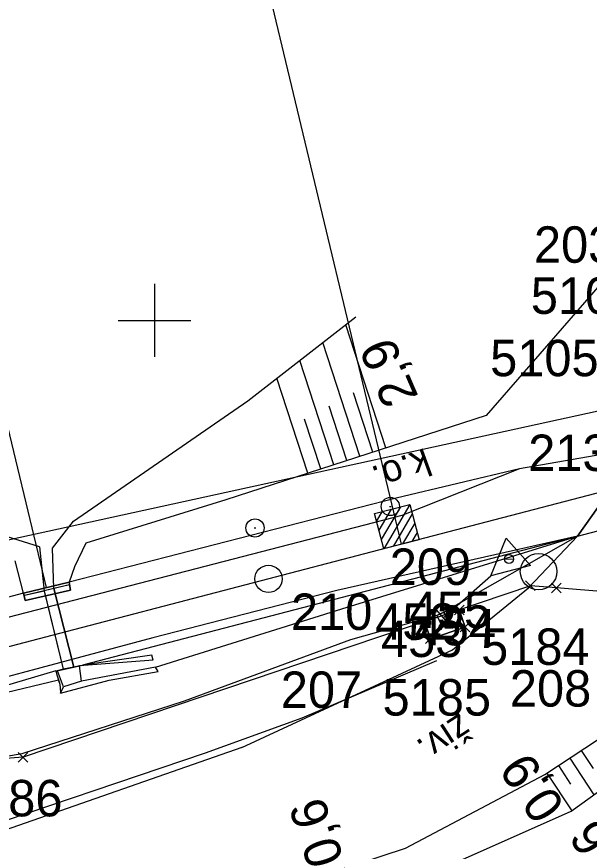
# Model space of a CAD drawing. Extents: x -806456 to -805395, y -1150847 to -1150506.
# Drawn here: x -806207.56 to -806176.16, y -1150729.15 to -1150683.33 of the extents above; entities that cross this region are included whole.
import ezdxf

# ---------------------------------------------------------------- set-up
doc = ezdxf.new("R2010")
doc.units = 0
for name, color, linetype in [('0381KM032-037P - Vrstva 1', 7, 'Continuous'), ('0381KM032-037P - Vrstva 12', 7, 'Continuous'), ('0381KM032-037P - Vrstva 13', 7, 'Continuous'), ('0381KM032-037P - Vrstva 17', 7, 'Continuous'), ('0381KM032-037P - Vrstva 19', 7, 'Continuous'), ('0381KM032-037P - Vrstva 27', 7, 'Continuous'), ('0381KM032-037P - Vrstva 3', 7, 'Continuous'), ('0381KM032-037P - Vrstva 4', 7, 'Continuous'), ('0381KM032-037P - Vrstva 43', 7, 'Continuous'), ('0381KM032-037P - Vrstva 48', 7, 'Continuous'), ('0381KM032-037P - Vrstva 49', 7, 'Continuous'), ('0381KM032-037P - Vrstva 51', 7, 'Continuous'), ('0381KM032-037P - Vrstva 7', 7, 'Continuous'), ('DZ - DZ_krizek', 7, 'Continuous'), ('DZ - DZ_ostat', 7, 'Continuous'), ('DZ - DZ_číslo', 7, 'Continuous'), ('krizky_1000 - Vrstva 1', 7, 'Continuous'), ('szdc - hran DP', 7, 'Continuous'), ('szdc - szdc_cislo', 7, 'Continuous'), ('szdc - szdc_krizek', 7, 'Continuous'), ('VB - VB', 7, 'Continuous'), ('VB - VB_cislo', 7, 'Continuous'), ('VB - VB_krizek', 7, 'Continuous')]:
    doc.layers.add(name, color=color, linetype=linetype)

msp = doc.modelspace()

# ---------------------------------------------------------------- linework, layer by layer
at = {"layer": '0381KM032-037P - Vrstva 1'}
msp.add_lwpolyline([(-805989.76, -1150661.17), (-806027.03, -1150670.9), (-806064.32, -1150680.56), (-806101.67, -1150690.24), (-806138.44, -1150699.75), (-806158.28, -1150704.94), (-806163.64, -1150706.34), (-806175.38, -1150709.4), (-806186.46, -1150712.29), (-806205.201, -1150717.188), (-806213.26, -1150719.29)], dxfattribs=at)
at = {"layer": '0381KM032-037P - Vrstva 12'}
for p, q in [((-806184.517, -1150716.193), (-806184.135, -1150716.013)), ((-806183.852, -1150716.584), (-806183.846, -1150716.582)), ((-806184.236, -1150716.767), (-806184.232, -1150716.767))]:
    msp.add_line(p, q, dxfattribs=at)
msp.add_lwpolyline([(-806184.517, -1150716.196), (-806184.136, -1150716.011), (-806183.846, -1150716.582), (-806184.232, -1150716.767), (-806184.517, -1150716.196), (-806184.517, -1150716.193), (-806184.236, -1150716.767), (-806183.852, -1150716.584), (-806184.135, -1150716.013), (-806184.136, -1150716.011)], dxfattribs=at)
at = {"layer": '0381KM032-037P - Vrstva 13'}
for p, q in [((-806200.148, -1150718.382), (-806203.948, -1150718.928)), ((-806200.065, -1150718.644), (-806200.148, -1150718.382)), ((-806200.065, -1150718.644), (-806204.115, -1150718.971)), ((-806204.115, -1150718.971), (-806203.948, -1150718.928)), ((-806203.996, -1150719.808), (-806204.115, -1150718.971)), ((-806204.985, -1150720.124), (-806205.321, -1150719.23)), ((-806203.996, -1150719.808), (-806204.985, -1150720.124))]:
    msp.add_line(p, q, dxfattribs=at)
for points in [[(-806204.115, -1150718.971), (-806204.42, -1150719.04), (-806205.012, -1150719.152), (-806205.321, -1150719.23)], [(-806205.415, -1150719.241), (-806205.341, -1150719.246), (-806205.321, -1150719.23)], [(-806205.415, -1150719.241), (-806205.331, -1150719.519), (-806205.259, -1150719.74), (-806205.211, -1150719.896), (-806205.18, -1150720.145), (-806205.147, -1150720.463), (-806204.985, -1150720.124)], [(-806205.147, -1150720.463), (-806202.482, -1150719.745), (-806199.79, -1150719.277), (-806199.947, -1150719.038), (-806203.996, -1150719.808)]]:
    msp.add_lwpolyline(points, dxfattribs=at)
at = {"layer": '0381KM032-037P - Vrstva 17'}
msp.add_line((-806191.898, -1150721.811), (-806184.517, -1150718.669), dxfattribs=at)
msp.add_lwpolyline([(-806210.617, -1150728.275), (-806197.196, -1150723.748), (-806191.898, -1150721.811)], dxfattribs=at)
at = {"layer": '0381KM032-037P - Vrstva 19'}
for p, q in [((-806205.929, -1150714.672), (-806217.278, -1150667.349)), ((-806204.679, -1150714.37), (-806207.178, -1150714.973)), ((-806206.05, -1150714.841), (-806205.013, -1150719.154)), ((-806205.518, -1150714.716), (-806205.523, -1150714.718)), ((-806204.418, -1150719.038), (-806205.523, -1150714.718)), ((-806205.518, -1150714.716), (-806204.42, -1150719.04)), ((-806204.606, -1150714.816), (-806204.652, -1150714.519)), ((-806206.05, -1150714.858), (-806207.127, -1150715.107)), ((-806207.086, -1150715.378), (-806207.127, -1150715.107)), ((-806206.05, -1150714.858), (-806205.012, -1150719.152)), ((-806205.013, -1150719.154), (-806204.418, -1150719.038))]:
    msp.add_line(p, q, dxfattribs=at)
for points in [[(-806204.682, -1150714.372), (-806204.679, -1150714.37), (-806204.652, -1150714.519), (-806207.127, -1150715.107), (-806207.178, -1150714.973), (-806207.177, -1150714.974)], [(-806204.682, -1150714.372), (-806204.606, -1150714.816), (-806207.086, -1150715.378), (-806207.177, -1150714.974), (-806204.682, -1150714.372)], [(-806205.523, -1150714.718), (-806206.05, -1150714.841), (-806206.05, -1150714.858)], [(-806204.652, -1150714.519), (-806205.518, -1150714.716)], [(-806205.341, -1150719.246), (-806203.948, -1150718.928)], [(-806204.418, -1150719.038), (-806204.42, -1150719.04), (-806204.115, -1150718.971), (-806203.948, -1150718.928)], [(-806205.012, -1150719.152), (-806205.321, -1150719.23), (-806205.341, -1150719.246)], [(-806205.013, -1150719.154), (-806205.012, -1150719.152)]]:
    msp.add_lwpolyline(points, dxfattribs=at)
at = {"layer": '0381KM032-037P - Vrstva 27'}
msp.add_line((-806187.119, -1150710.216), (-806187.019, -1150710.216), dxfattribs=at)
msp.add_circle((-806187.069, -1150710.216), 0.5, dxfattribs=at)
at = {"layer": '0381KM032-037P - Vrstva 3'}
for p, q in [((-806186.46, -1150712.29), (-806198.557, -1150661.727)), ((-806186.51, -1150710.236), (-806187.561, -1150712.03)), ((-806185.997, -1150710.102), (-806187.428, -1150712.542)), ((-806187.537, -1150710.504), (-806187.829, -1150711.003)), ((-806187.024, -1150710.37), (-806187.695, -1150711.516)), ((-806185.863, -1150710.615), (-806186.915, -1150712.409)), ((-806185.729, -1150711.129), (-806186.401, -1150712.275)), ((-806185.596, -1150711.642), (-806185.888, -1150712.141))]:
    msp.add_line(p, q, dxfattribs=at)
msp.add_lwpolyline([(-806185.492, -1150712.038), (-806187.428, -1150712.542), (-806187.932, -1150710.607), (-806185.997, -1150710.102)], close=True, dxfattribs=at)
at = {"layer": '0381KM032-037P - Vrstva 4'}
for p, q in [((-806176.794, -1150711.837), (-806203.948, -1150718.928)), ((-806180.805, -1150713.083), (-806180.317, -1150713.117)), ((-806184.68, -1150715.748), (-806183.652, -1150716.916))]:
    msp.add_line(p, q, dxfattribs=at)
msp.add_lwpolyline([(-806165.452, -1150708.868), (-806162.708, -1150704.236), (-806173.358, -1150707), (-806176.794, -1150711.837)], close=True, dxfattribs=at)
for points in [[(-806173.358, -1150707), (-806179.992, -1150708.144), (-806186.437, -1150710.716), (-806215.256, -1150718.168), (-806230.349, -1150722.089), (-806238.693, -1150724.411)], [(-806179.992, -1150708.144), (-806186.747, -1150709.759), (-806204.682, -1150714.372)], [(-806176.794, -1150711.837), (-806190.006, -1150714.82), (-806200.085, -1150717.418), (-806214.718, -1150721.345), (-806229.528, -1150725.211), (-806238.55, -1150727.775)], [(-806184.166, -1150716.332), (-806181.562, -1150714.027), (-806180.714, -1150711.959), (-806179.386, -1150713.451), (-806181.562, -1150714.027)], [(-806207.177, -1150714.974), (-806207.086, -1150715.378), (-806204.606, -1150714.816), (-806204.682, -1150714.372)], [(-806207.177, -1150714.974), (-806215.394, -1150717.144), (-806230.58, -1150720.973), (-806238.74, -1150723.305)], [(-806205.415, -1150719.241), (-806205.341, -1150719.246), (-806203.948, -1150718.928)], [(-806205.415, -1150719.241), (-806214.6, -1150721.97), (-806229.14, -1150726.003), (-806238.515, -1150728.599)]]:
    msp.add_lwpolyline(points, dxfattribs=at)
msp.add_circle((-806180.562, -1150713.101), 0.248, dxfattribs=at)
at = {"layer": '0381KM032-037P - Vrstva 43'}
msp.add_circle((-806178.939, -1150713.793), 1, dxfattribs=at)
at = {"layer": '0381KM032-037P - Vrstva 48'}
for p, q in [((-806187.315, -1150706.999), (-806189.508, -1150700.237)), ((-806188.741, -1150707.462), (-806190.768, -1150701.216)), ((-806190.168, -1150707.925), (-806192.027, -1150702.196)), ((-806191.595, -1150708.388), (-806193.286, -1150703.176)), ((-806188.028, -1150707.231), (-806189.083, -1150703.978)), ((-806189.455, -1150707.693), (-806190.426, -1150704.7)), ((-806190.882, -1150708.156), (-806191.769, -1150705.421)), ((-806176.597, -1150723.612), (-806175.943, -1150724.607)), ((-806177.85, -1150724.435), (-806177.18, -1150725.456)), ((-806177.223, -1150724.024), (-806175.899, -1150726.04)), ((-806178.477, -1150724.847), (-806177.119, -1150726.915))]:
    msp.add_line(p, q, dxfattribs=at)
at = {"layer": '0381KM032-037P - Vrstva 49'}
for p, q in [((-806207.177, -1150714.974), (-806207.636, -1150713.191)), ((-806204.393, -1150713.538), (-806204.682, -1150714.372)), ((-806214.6, -1150721.97), (-806205.259, -1150719.74)), ((-806205.211, -1150719.896), (-806205.259, -1150719.74))]:
    msp.add_line(p, q, dxfattribs=at)
for points in [[(-806157.224, -1150688.717), (-806163.106, -1150693.208), (-806169.402, -1150695.384), (-806175.562, -1150698.028), (-806181.812, -1150705.214), (-806196.093, -1150709.847), (-806203.772, -1150712.233), (-806204.393, -1150713.538)], [(-806205.585, -1150712.508), (-806204.437, -1150711.021), (-806194.881, -1150704.417), (-806188.959, -1150699.809)], [(-806206.314, -1150712.425), (-806211.288, -1150710.871), (-806222.32, -1150713.908), (-806237.293, -1150717.516), (-806238.963, -1150718.052)], [(-806176.794, -1150711.837), (-806184.135, -1150716.013), (-806184.517, -1150716.193), (-806189.244, -1150717.541), (-806198.367, -1150720.903), (-806207.279, -1150723.797), (-806228.886, -1150727.595), (-806238.447, -1150730.204)], [(-806205.211, -1150719.896), (-806205.18, -1150720.145), (-806205.147, -1150720.463), (-806202.482, -1150719.745), (-806199.79, -1150719.277), (-806199.947, -1150719.038), (-806189.725, -1150715.834), (-806176.794, -1150711.837)], [(-806206.314, -1150712.425), (-806206.05, -1150714.858), (-806207.127, -1150715.107), (-806207.178, -1150714.973), (-806207.177, -1150714.974)], [(-806204.682, -1150714.372), (-806204.679, -1150714.37), (-806204.652, -1150714.519), (-806205.518, -1150714.716), (-806205.585, -1150712.508)], [(-806193.249, -1150733.077), (-806185.745, -1150730.772), (-806177.154, -1150726.94), (-806171.988, -1150723.234), (-806169.987, -1150720.615)], [(-806194.182, -1150731.583), (-806186.226, -1150728.982), (-806178.594, -1150724.924), (-806174.208, -1150722.043)]]:
    msp.add_lwpolyline(points, dxfattribs=at)
at = {"layer": '0381KM032-037P - Vrstva 51'}
msp.add_line((-806195.218, -1150723.443), (-806210.458, -1150728.774), dxfattribs=at)
for points in [[(-806195.218, -1150723.443), (-806183.651, -1150718.077), (-806179.484, -1150714.678), (-806176.794, -1150711.837), (-806173.358, -1150707), (-806168.375, -1150700.145), (-806163.106, -1150693.208), (-806157.224, -1150688.717), (-806150.874, -1150685.207), (-806140.159, -1150681.153)], [(-806194.182, -1150731.583), (-806186.226, -1150728.982), (-806178.594, -1150724.924), (-806174.208, -1150722.043), (-806171.128, -1150719.056), (-806168.37, -1150714.464), (-806165.452, -1150708.868), (-806162.708, -1150704.236), (-806160.94, -1150702.044), (-806159.44, -1150700.497), (-806157.039, -1150698.345), (-806150.424, -1150694.243), (-806141.479, -1150690.749), (-806131.125, -1150687.358), (-806121.483, -1150684.155)]]:
    msp.add_lwpolyline(points, dxfattribs=at)
at = {"layer": '0381KM032-037P - Vrstva 7'}
msp.add_line((-806194.541, -1150711.396), (-806194.441, -1150711.396), dxfattribs=at)
for centre, radius in [((-806194.491, -1150711.396), 0.5), ((-806193.746, -1150714.193), 0.75)]:
    msp.add_circle(centre, radius, dxfattribs=at)
at = {"layer": 'DZ - DZ_krizek'}
for p, q in [((-806183.024, -1150716.157), (-806183.555, -1150715.627)), ((-806183.555, -1150716.157), (-806183.024, -1150715.627)), ((-806184.919, -1150716.797), (-806185.45, -1150716.267)), ((-806185.45, -1150716.797), (-806184.919, -1150716.267)), ((-806182.704, -1150717.104), (-806183.235, -1150716.574)), ((-806183.235, -1150717.104), (-806182.704, -1150716.574)), ((-806184.598, -1150717.745), (-806185.129, -1150717.215)), ((-806185.129, -1150717.745), (-806184.598, -1150717.215))]:
    msp.add_line(p, q, dxfattribs=at)
at = {"layer": 'DZ - DZ_ostat'}
for p, q in [((-806185.184, -1150716.532), (-806183.289, -1150715.892)), ((-806182.969, -1150716.839), (-806183.289, -1150715.892)), ((-806183.289, -1150715.892), (-806182.969, -1150716.839)), ((-806184.863, -1150717.48), (-806185.184, -1150716.532)), ((-806184.863, -1150717.48), (-806182.969, -1150716.839)), ((-806182.969, -1150716.839), (-806184.863, -1150717.48))]:
    msp.add_line(p, q, dxfattribs=at)
msp.add_lwpolyline([(-806184.863, -1150717.48), (-806185.184, -1150716.532), (-806183.289, -1150715.892)], dxfattribs=at)
at = {"layer": 'krizky_1000 - Vrstva 1'}
for points in [[(-806200, -1150698), (-806200, -1150702)], [(-806202, -1150700), (-806198, -1150700)]]:
    msp.add_lwpolyline(points, dxfattribs=at)
at = {"layer": 'szdc - hran DP'}
for p, q in [((-806238.93, -1150718.822), (-806172.99, -1150704.37)), ((-806179.38, -1150714.57), (-806207.21, -1150723.98)), ((-806177.96, -1150714.69), (-806179.38, -1150714.57)), ((-806169.25, -1150715.39), (-806177.96, -1150714.69)), ((-806207.21, -1150723.98), (-806212.4, -1150724.39))]:
    msp.add_line(p, q, dxfattribs=at)
at = {"layer": 'szdc - szdc_krizek'}
for p, q in [((-806179.115, -1150714.835), (-806179.646, -1150714.305)), ((-806179.646, -1150714.835), (-806179.115, -1150714.305)), ((-806177.695, -1150714.955), (-806178.226, -1150714.425)), ((-806178.226, -1150714.955), (-806177.695, -1150714.425)), ((-806206.945, -1150724.245), (-806207.476, -1150723.715)), ((-806207.476, -1150724.245), (-806206.945, -1150723.715))]:
    msp.add_line(p, q, dxfattribs=at)
at = {"layer": 'VB - VB'}
msp.add_line((-806185.184, -1150716.532), (-806183.289, -1150715.892), dxfattribs=at)
msp.add_lwpolyline([(-806185.184, -1150716.532), (-806184.863, -1150717.48), (-806182.969, -1150716.839), (-806183.289, -1150715.892)], dxfattribs=at)
at = {"layer": 'VB - VB_krizek'}
for p, q in [((-806183.024, -1150716.157), (-806183.555, -1150715.627)), ((-806183.555, -1150716.157), (-806183.024, -1150715.627)), ((-806184.919, -1150716.797), (-806185.45, -1150716.267)), ((-806185.45, -1150716.797), (-806184.919, -1150716.267)), ((-806182.704, -1150717.104), (-806183.235, -1150716.574)), ((-806183.235, -1150717.104), (-806182.704, -1150716.574)), ((-806184.598, -1150717.745), (-806185.129, -1150717.215)), ((-806185.129, -1150717.745), (-806184.598, -1150717.215))]:
    msp.add_line(p, q, dxfattribs=at)

# ---------------------------------------------------------------- texts
at = {"layer": '0381KM032-037P - Vrstva 27'}
msp.add_text('k.o.', height=1.5, rotation=200, dxfattribs=at).set_placement((-806185.171, -1150706.984))
at = {"layer": '0381KM032-037P - Vrstva 48'}
for s, rotation, p in [('2,9', 113.3885, (-806185.505, -1150704.194)), ('0,9', 123.4305, (-806177.439, -1150726.673)), ('0,6', 108.1038, (-806189.601, -1150729.604)), ('4,6', 126.74, (-806173.521, -1150730.195))]:
    msp.add_text(s, height=2, rotation=rotation, dxfattribs=at).set_placement(p)
at = {"layer": '0381KM032-037P - Vrstva 51'}
msp.add_text('živ.', height=1.5, rotation=213, dxfattribs=at).set_placement((-806183.234, -1150721.52))
at = {"layer": 'DZ - DZ_číslo'}
for s, p in [('203', (-806179.191, -1150696.837)), ('213', (-806179.506, -1150708.269)), ('209', (-806187.097, -1150714.522)), ('210', (-806192.515, -1150716.995)), ('207', (-806193.073, -1150721.274)), ('208', (-806180.512, -1150721.201))]:
    msp.add_text(s, height=2, dxfattribs=at).set_placement(p)
at = {"layer": 'szdc - szdc_cislo'}
for s, p in [('5106', (-806179.362, -1150699.642)), ('5105', (-806181.593, -1150703.065)), ('5184', (-806182.089, -1150718.912)), ('5185', (-806187.493, -1150721.694)), ('5186', (-806210.996, -1150727.227))]:
    msp.add_text(s, height=2, dxfattribs=at).set_placement(p)
at = {"layer": 'VB - VB_cislo'}
for s, p in [('455', (-806186.005, -1150716.892)), ('452', (-806187.9, -1150717.532)), ('454', (-806185.733, -1150717.839)), ('453', (-806187.579, -1150718.48))]:
    msp.add_text(s, height=2, dxfattribs=at).set_placement(p)

doc.saveas('drawing.dxf')
